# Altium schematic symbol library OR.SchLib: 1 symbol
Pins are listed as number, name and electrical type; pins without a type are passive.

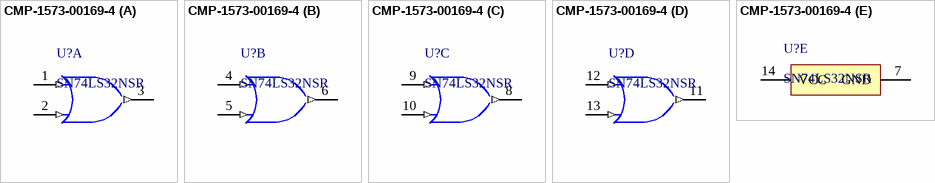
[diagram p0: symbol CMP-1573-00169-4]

## CMP-1573-00169-4
designator U?, comment SN74LS32NSR
Quad 2-input positive-OR gates, NS0014A, LARGE T&R; Manufacturer: Texas Instruments; VCC(Max)(V): 5.25; VCC(Min)(V): 4.75; Input Type: TTL; Output Drive (IOL/IOH)(Max)(mA): 0.8/-16; Bits(#): 4; Rating: Catalog; ICC @ Nom Voltage(Max)(mA): 0.038; F @ Nom Voltage(Max)(Mhz): 35; Voltage(Nom)(V): 5; tpd @ Nom Voltage(Max)(ns): 22
footprint NS0014A_M (SOIC,14-Leads,Body 10.5x5.6mm,Pitch 1.27mm,IPC Low Density)
footprint NS0014A_L (SOP, 14-Leads, Body 10.2x5.3mm, Pitch 1.27mm, IPC High Density)
footprint NS0014A_N (SOIC,14-Leads,Body 10.5x5.6mm,Pitch 1.27mm,IPC Medium Density)
part A pins: 1 1A (in), 2 1B (in), 3 1Y (out)
part B pins: 4 2A (in), 5 2B (in), 6 2Y (out)
part C pins: 8 3Y (out), 9 3A (in), 10 3B (in)
part D pins: 11 4Y (out), 12 4A (in), 13 4B (in)
part E pins: 7 GND (power), 14 VCC (power)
